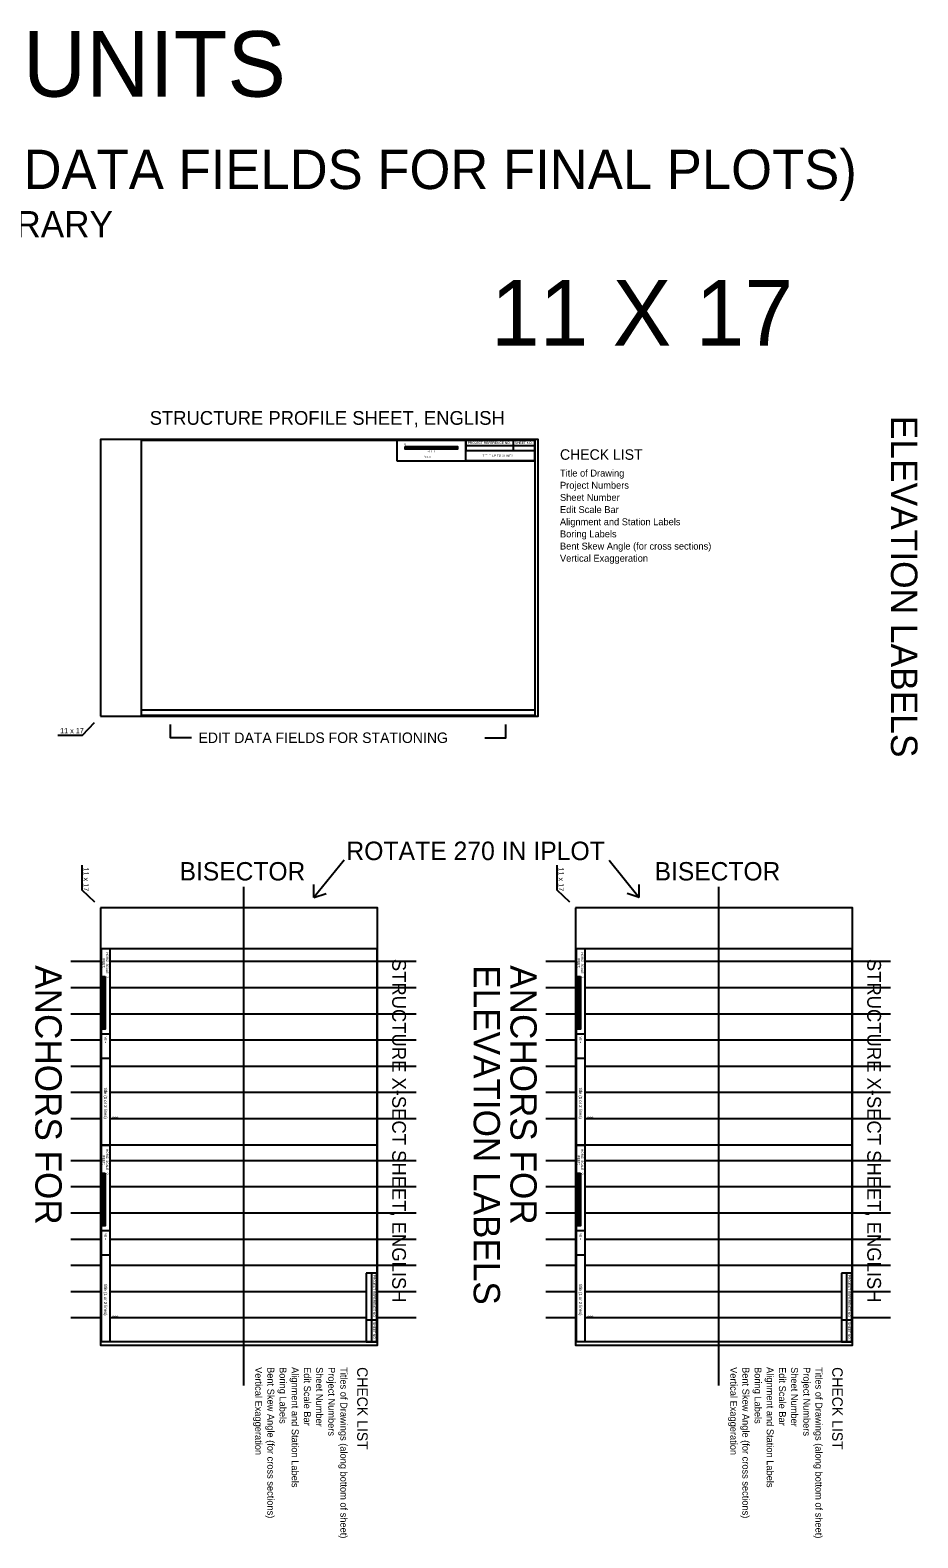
# Model space of a CAD drawing. Extents: x 278618 to 280654, y 171155 to 171855.
# Drawn here: x 279201 to 279539, y 171208 to 171783 of the extents above; entities that cross this region are included whole.
import ezdxf

# ---------------------------------------------------------------- set-up
doc = ezdxf.new("R2010")
doc.units = 0
for name, color, linetype in [('Geotech Sheets and Borders Cell', 7, 'Continuous'), ('Prop Strc Sect_ Grid - minor', 7, 'Continuous'), ('Prop Strc Sect_ Misc - Drafting Aid (dashed line)', 7, 'Continuous'), ('Prop Strc Sect_ Misc - User Comment (Tx - large)', 7, 'Continuous'), ('Prop Strc Sect_ Misc - User Comment (Tx - small)', 7, 'Continuous'), ('Scratch_Level_0', 7, 'Continuous'), ('Scratch_Level_2', 7, 'Continuous'), ('Scratch_Level_4', 7, 'Continuous'), ('Sheet Plot Border Inside CELL', 7, 'Continuous')]:
    doc.layers.add(name, color=color, linetype=linetype)

msp = doc.modelspace()

# ---------------------------------------------------------------- linework, layer by layer
at = {"layer": 'Geotech Sheets and Borders Cell'}
for p, q in [((279366.85, 171624.51), (279393.15, 171624.51)), ((279384.86, 171626.51), (279384.86, 171622.51)), ((279243.15, 171523.66), (279393.15, 171523.66)), ((279231.12, 171399.92), (279227.92, 171399.92)), ((279231.12, 171399.92), (279227.92, 171399.92)), ((279412.21, 171399.92), (279409, 171399.92)), ((279412.21, 171399.92), (279409, 171399.92)), ((279231.12, 171390.69), (279227.92, 171390.69)), ((279412.21, 171390.69), (279409, 171390.69)), ((279332.92, 171357.58), (279227.92, 171357.58)), ((279514, 171357.58), (279409, 171357.58)), ((279231.12, 171324.92), (279227.92, 171324.92)), ((279412.21, 171324.92), (279409, 171324.92)), ((279231.12, 171315.69), (279227.92, 171315.69)), ((279412.21, 171315.69), (279409, 171315.69)), ((279330.92, 171308.88), (279330.92, 171282.58)), ((279512, 171308.88), (279512, 171282.58)), ((279332.92, 171290.87), (279328.92, 171290.87)), ((279514, 171290.87), (279510, 171290.87))]:
    msp.add_line(p, q, dxfattribs=at)
for points in [[(279243.15, 171626.51), (279393.15, 171626.51), (279393.15, 171521.51), (279243.15, 171521.51)], [(279340.56, 171618.61), (279393.15, 171618.61), (279393.15, 171626.51), (279340.56, 171626.51)], [(279343.7, 171624.05), (279363.7, 171624.05), (279363.7, 171623.05), (279343.7, 171623.05)], [(279343.7, 171624.05), (279353.7, 171624.05), (279353.7, 171623.55), (279343.7, 171623.55)], [(279366.85, 171622.51), (279393.15, 171622.51), (279393.15, 171626.51), (279366.85, 171626.51)], [(279366.85, 171626.51), (279393.15, 171626.51), (279393.15, 171618.61), (279366.85, 171618.61)], [(279353.7, 171623.55), (279363.7, 171623.55), (279363.7, 171623.05), (279353.7, 171623.05)], [(279332.92, 171432.58), (279332.92, 171282.58), (279227.92, 171282.58), (279227.92, 171432.58)], [(279231.12, 171432.58), (279231.12, 171357.58), (279227.92, 171357.58), (279227.92, 171432.58)], [(279514, 171432.58), (279514, 171282.58), (279409, 171282.58), (279409, 171432.58)], [(279412.21, 171432.58), (279412.21, 171357.58), (279409, 171357.58), (279409, 171432.58)], [(279229.41, 171421.9), (279229.41, 171401.9), (279228.41, 171401.9), (279228.41, 171421.9)], [(279229.41, 171421.9), (279229.41, 171411.9), (279228.91, 171411.9), (279228.91, 171421.9)], [(279410.5, 171421.9), (279410.5, 171401.9), (279409.5, 171401.9), (279409.5, 171421.9)], [(279410.5, 171421.9), (279410.5, 171411.9), (279410, 171411.9), (279410, 171421.9)], [(279228.91, 171411.9), (279228.91, 171401.9), (279228.41, 171401.9), (279228.41, 171411.9)], [(279410, 171411.9), (279410, 171401.9), (279409.5, 171401.9), (279409.5, 171411.9)], [(279231.12, 171357.58), (279231.12, 171282.58), (279227.92, 171282.58), (279227.92, 171357.58)], [(279412.21, 171357.58), (279412.21, 171282.58), (279409, 171282.58), (279409, 171357.58)], [(279229.41, 171346.9), (279229.41, 171326.9), (279228.41, 171326.9), (279228.41, 171346.9)], [(279229.41, 171346.9), (279229.41, 171336.9), (279228.91, 171336.9), (279228.91, 171346.9)], [(279410.5, 171346.9), (279410.5, 171326.9), (279409.5, 171326.9), (279409.5, 171346.9)], [(279410.5, 171346.9), (279410.5, 171336.9), (279410, 171336.9), (279410, 171346.9)], [(279228.91, 171336.9), (279228.91, 171326.9), (279228.41, 171326.9), (279228.41, 171336.9)], [(279410, 171336.9), (279410, 171326.9), (279409.5, 171326.9), (279409.5, 171336.9)], [(279328.92, 171308.88), (279328.92, 171282.58), (279332.92, 171282.58), (279332.92, 171308.88)], [(279510, 171308.88), (279510, 171282.58), (279514, 171282.58), (279514, 171308.88)]]:
    msp.add_lwpolyline(points, close=True, dxfattribs=at)
at = {"layer": 'Prop Strc Sect_ Grid - minor'}
for p, q in [((279332.92, 171427.66), (279231.12, 171427.66)), ((279514, 171427.66), (279412.21, 171427.66)), ((279332.92, 171417.66), (279231.12, 171417.66)), ((279514, 171417.66), (279412.21, 171417.66)), ((279332.92, 171407.66), (279231.12, 171407.66)), ((279514, 171407.66), (279412.21, 171407.66)), ((279332.92, 171397.66), (279231.12, 171397.66)), ((279514, 171397.66), (279412.21, 171397.66)), ((279332.92, 171387.66), (279231.12, 171387.66)), ((279514, 171387.66), (279412.21, 171387.66)), ((279332.92, 171377.66), (279231.12, 171377.66)), ((279514, 171377.66), (279412.21, 171377.66)), ((279332.92, 171367.66), (279231.12, 171367.66)), ((279514, 171367.66), (279412.21, 171367.66)), ((279332.92, 171351.72), (279231.12, 171351.72)), ((279514, 171351.72), (279412.21, 171351.72)), ((279332.92, 171341.72), (279231.12, 171341.72)), ((279514, 171341.72), (279412.21, 171341.72)), ((279332.92, 171331.72), (279231.12, 171331.72)), ((279514, 171331.72), (279412.21, 171331.72)), ((279332.92, 171321.72), (279231.12, 171321.72)), ((279514, 171321.72), (279412.21, 171321.72)), ((279332.92, 171311.72), (279231.12, 171311.72)), ((279514, 171311.72), (279412.21, 171311.72)), ((279328.92, 171301.72), (279231.12, 171301.72)), ((279510, 171301.72), (279412.21, 171301.72)), ((279328.92, 171291.72), (279231.12, 171291.72)), ((279510, 171291.72), (279412.21, 171291.72))]:
    msp.add_line(p, q, dxfattribs=at)
at = {"layer": 'Prop Strc Sect_ Misc - Drafting Aid (dashed line)'}
for p, q in [((279282.08, 171456.11), (279282.08, 171265.99)), ((279463.17, 171456.11), (279463.17, 171265.99)), ((279227.92, 171427.66), (279216.29, 171427.66)), ((279233.2, 171427.66), (279231.12, 171427.66)), ((279347.88, 171427.66), (279330.96, 171427.66)), ((279409, 171427.66), (279397.38, 171427.66)), ((279414.29, 171427.66), (279412.21, 171427.66)), ((279528.75, 171427.66), (279511.83, 171427.66)), ((279227.92, 171417.66), (279216.29, 171417.66)), ((279233.2, 171417.66), (279231.12, 171417.66)), ((279347.88, 171417.66), (279330.96, 171417.66)), ((279409, 171417.66), (279397.38, 171417.66)), ((279414.29, 171417.66), (279412.21, 171417.66)), ((279528.75, 171417.66), (279511.83, 171417.66)), ((279227.92, 171407.66), (279216.29, 171407.66)), ((279233.2, 171407.66), (279231.12, 171407.66)), ((279347.88, 171407.66), (279330.96, 171407.66)), ((279409, 171407.66), (279397.38, 171407.66)), ((279414.29, 171407.66), (279412.21, 171407.66)), ((279528.75, 171407.66), (279511.83, 171407.66)), ((279227.92, 171397.66), (279216.29, 171397.66)), ((279233.2, 171397.66), (279231.12, 171397.66)), ((279347.88, 171397.66), (279330.96, 171397.66)), ((279409, 171397.66), (279397.38, 171397.66)), ((279414.29, 171397.66), (279412.21, 171397.66)), ((279528.75, 171397.66), (279511.83, 171397.66)), ((279227.92, 171387.66), (279216.29, 171387.66)), ((279233.2, 171387.66), (279231.12, 171387.66)), ((279347.88, 171387.66), (279330.96, 171387.66)), ((279409, 171387.66), (279397.38, 171387.66)), ((279414.29, 171387.66), (279412.21, 171387.66)), ((279528.75, 171387.66), (279511.83, 171387.66)), ((279227.92, 171377.66), (279216.29, 171377.66)), ((279233.2, 171377.66), (279231.12, 171377.66)), ((279347.88, 171377.66), (279330.96, 171377.66)), ((279409, 171377.66), (279397.38, 171377.66)), ((279414.29, 171377.66), (279412.21, 171377.66)), ((279528.75, 171377.66), (279511.83, 171377.66)), ((279227.92, 171367.66), (279216.29, 171367.66)), ((279233.2, 171367.66), (279231.12, 171367.66)), ((279347.88, 171367.66), (279330.96, 171367.66)), ((279409, 171367.66), (279397.38, 171367.66)), ((279414.29, 171367.66), (279412.21, 171367.66)), ((279528.75, 171367.66), (279511.83, 171367.66)), ((279227.92, 171351.72), (279216.29, 171351.72)), ((279233.2, 171351.72), (279231.12, 171351.72)), ((279347.88, 171351.72), (279330.96, 171351.72)), ((279409, 171351.72), (279397.38, 171351.72)), ((279414.29, 171351.72), (279412.21, 171351.72)), ((279528.75, 171351.72), (279511.83, 171351.72)), ((279227.92, 171341.72), (279216.29, 171341.72)), ((279233.2, 171341.72), (279231.12, 171341.72)), ((279347.88, 171341.72), (279330.96, 171341.72)), ((279409, 171341.72), (279397.38, 171341.72)), ((279414.29, 171341.72), (279412.21, 171341.72)), ((279528.75, 171341.72), (279511.83, 171341.72)), ((279227.92, 171331.72), (279216.29, 171331.72)), ((279233.2, 171331.72), (279231.12, 171331.72)), ((279347.88, 171331.72), (279330.96, 171331.72)), ((279409, 171331.72), (279397.38, 171331.72)), ((279414.29, 171331.72), (279412.21, 171331.72)), ((279528.75, 171331.72), (279511.83, 171331.72)), ((279227.92, 171321.72), (279216.29, 171321.72)), ((279233.2, 171321.72), (279231.12, 171321.72)), ((279347.88, 171321.72), (279330.96, 171321.72)), ((279409, 171321.72), (279397.38, 171321.72)), ((279414.29, 171321.72), (279412.21, 171321.72)), ((279528.75, 171321.72), (279511.83, 171321.72)), ((279227.92, 171311.72), (279216.29, 171311.72)), ((279233.2, 171311.72), (279231.12, 171311.72)), ((279347.88, 171311.72), (279330.96, 171311.72)), ((279409, 171311.72), (279397.38, 171311.72)), ((279414.29, 171311.72), (279412.21, 171311.72)), ((279528.75, 171311.72), (279511.83, 171311.72)), ((279227.92, 171301.72), (279216.29, 171301.72)), ((279233.2, 171301.72), (279231.12, 171301.72)), ((279347.88, 171301.72), (279332.92, 171301.72)), ((279409, 171301.72), (279397.38, 171301.72)), ((279414.29, 171301.72), (279412.21, 171301.72)), ((279528.75, 171301.72), (279514, 171301.72)), ((279227.92, 171291.72), (279216.29, 171291.72)), ((279233.2, 171291.72), (279231.12, 171291.72)), ((279347.88, 171291.72), (279332.92, 171291.72)), ((279409, 171291.72), (279397.38, 171291.72)), ((279414.29, 171291.72), (279412.21, 171291.72)), ((279528.75, 171291.72), (279514, 171291.72))]:
    msp.add_line(p, q, dxfattribs=at)
at = {"layer": 'Prop Strc Sect_ Misc - User Comment (Tx - small)'}
for p, q in [((279320.49, 171466.35), (279308.95, 171452.11)), ((279421.43, 171466.35), (279432.97, 171452.11)), ((279308.95, 171452.11), (279308.95, 171457)), ((279308.95, 171452.11), (279313.61, 171453.59)), ((279432.97, 171452.11), (279428.31, 171453.59)), ((279432.97, 171452.11), (279432.97, 171457))]:
    msp.add_line(p, q, dxfattribs=at)
at = {"layer": 'Scratch_Level_0'}
for p, q in [((279394.4, 171626.79), (279394.4, 171626.79)), ((279227.63, 171521.23), (279227.63, 171521.23)), ((279227.63, 171448.1), (279227.63, 171448.1)), ((279408.72, 171448.1), (279408.72, 171448.1)), ((279333.2, 171281.33), (279333.2, 171281.33)), ((279514.29, 171281.33), (279514.29, 171281.33))]:
    msp.add_line(p, q, dxfattribs=at)
for points in [[(279211.37, 171514.04), (279220.75, 171514.04), (279225.34, 171518.83)], [(279220.44, 171464.37), (279220.44, 171454.98), (279225.24, 171450.39)], [(279401.53, 171464.37), (279401.53, 171454.98), (279406.33, 171450.39)]]:
    msp.add_lwpolyline(points, dxfattribs=at)
at = {"layer": 'Scratch_Level_4'}
for points in [[(279262.24, 171513.02), (279254.21, 171513.02), (279254.21, 171518.1)], [(279374.06, 171513.02), (279382.08, 171513.02), (279382.08, 171518.1)]]:
    msp.add_lwpolyline(points, dxfattribs=at)
at = {"layer": 'Sheet Plot Border Inside CELL'}
for points in [[(279227.63, 171521.23), (279394.4, 171521.23), (279394.4, 171626.79), (279227.63, 171626.79)], [(279227.63, 171448.1), (279227.63, 171281.33), (279333.2, 171281.33), (279333.2, 171448.1)], [(279408.72, 171448.1), (279408.72, 171281.33), (279514.29, 171281.33), (279514.29, 171448.1)]]:
    msp.add_lwpolyline(points, close=True, dxfattribs=at)

# ---------------------------------------------------------------- texts
at = {"layer": 'Geotech Sheets and Borders Cell'}
for s, height, p in [('0', 0.84, (279343.46, 171624.52)), ('PROJECT REFERENCE NO.', 0.9, (279367.56, 171625.06)), ('SHEET NO.', 0.9, (279385.58, 171625.06)), ('VE =  ', 0.84, (279351, 171619.82)), ('FEET', 0.84, (279352.15, 171621.83)), ('###', 1.008, (279232.03, 171367.66)), ('###', 1.008, (279413.11, 171367.66)), ('###', 1.008, (279232.03, 171291.72)), ('###', 1.008, (279413.11, 171291.72))]:
    msp.add_text(s, height=height, dxfattribs=at).set_placement(p)
for s, height, rotation, p in [('TITLE UP TO 3 LINES', 0.84, 360, (279373.28, 171620.16)), ('(FEET)', 0.84, 270, (279228.46, 171428.93)), ('HORIZ. SCALE', 0.84, 270, (279229.7, 171431.14)), ('(FEET)', 0.84, 270, (279409.54, 171428.93)), ('HORIZ. SCALE', 0.84, 270, (279410.79, 171431.14)), ('0', 0.84, 270, (279229.89, 171422.14)), ('0', 0.84, 270, (279410.97, 171422.14)), ('VE =  ', 0.84, 270, (279229.08, 171399.07)), ('VE =  ', 0.84, 270, (279410.16, 171399.07)), ('title (1 or 2 lines) ', 1.1681, 270, (279228.91, 171379.6)), ('title (1 or 2 lines) ', 1.1681, 270, (279410, 171379.6)), ('(FEET)', 0.84, 270, (279228.46, 171353.93)), ('HORIZ. SCALE', 0.84, 270, (279229.7, 171356.14)), ('(FEET)', 0.84, 270, (279409.54, 171353.93)), ('HORIZ. SCALE', 0.84, 270, (279410.79, 171356.14)), ('0', 0.84, 270, (279229.89, 171347.14)), ('0', 0.84, 270, (279410.97, 171347.14)), ('VE =  ', 0.84, 270, (279229.08, 171324.07)), ('VE =  ', 0.84, 270, (279410.16, 171324.07)), ('PROJECT REFERENCE NO.', 0.9, 270, (279331.47, 171308.17)), ('PROJECT REFERENCE NO.', 0.9, 270, (279512.55, 171308.17)), ('title (1 or 2 lines) ', 1.1681, 270, (279228.91, 171304.6)), ('title (1 or 2 lines) ', 1.1681, 270, (279410, 171304.6)), ('SHEET NO.', 0.9, 270, (279331.47, 171290.16)), ('SHEET NO.', 0.9, 270, (279512.55, 171290.16))]:
    msp.add_text(s, height=height, rotation=rotation, dxfattribs=at).set_placement(p)
at = {"layer": 'Prop Strc Sect_ Misc - User Comment (Tx - large)'}
for s, height, p in [('ENGLISH UNITS', 25, (279041.91, 171757.51)), ('(TURN OFF DRAFTING AID LEVELS and DATA FIELDS FOR FINAL PLOTS)', 15, (278817.07, 171722.28)), ('11 X 17', 25, (279376.38, 171662.6))]:
    msp.add_text(s, height=height, dxfattribs=at).set_placement(p)
at = {"layer": 'Prop Strc Sect_ Misc - User Comment (Tx - small)'}
for s, height, p in [('ELEMENT LIBRARY', 10, (279108.22, 171703.88)), ('ROTATE 270 IN IPLOT', 7.0538, (279321.29, 171466.35)), ('BISECTOR', 7.009, (279257.74, 171458.59)), ('BISECTOR', 7.009, (279438.83, 171458.59))]:
    msp.add_text(s, height=height, dxfattribs=at).set_placement(p)
for s, height, p in [('ELEVATION LABELS', 10.0769, (279528.93, 171635.81)), ('ANCHORS FOR', 10.0124, (279202.77, 171426.25)), ('ELEVATION LABELS', 10.0124, (279369.84, 171426.25)), ('ANCHORS FOR', 10.0124, (279383.86, 171426.25))]:
    msp.add_text(s, height=height, rotation=270, dxfattribs=at).set_placement(p)
at = {"layer": 'Scratch_Level_0'}
msp.add_text('11 x 17', height=2, dxfattribs=at).set_placement((279212.18, 171514.71))
for p in [(279221.11, 171463.55), (279402.2, 171463.55)]:
    msp.add_text('11 x 17', height=2, rotation=270, dxfattribs=at).set_placement(p)
at = {"layer": 'Scratch_Level_2'}
msp.add_text('STRUCTURE PROFILE SHEET, ENGLISH', height=5.25, dxfattribs=at).set_placement((279246.34, 171632.37))
for p in [(279338.78, 171428.69), (279519.87, 171428.69)]:
    msp.add_text('STRUCTURE X-SECT SHEET, ENGLISH', height=5.25, rotation=270, dxfattribs=at).set_placement(p)
at = {"layer": 'Scratch_Level_4'}
for s, height, p in [('CHECK LIST', 4, (279402.74, 171619.03)), ('Title of Drawing', 2.64, (279402.74, 171612.63)), ('Project Numbers', 2.64, (279402.74, 171607.99)), ('Sheet Number', 2.64, (279402.74, 171603.35)), ('Edit Scale Bar', 2.64, (279402.74, 171598.71)), ('Alignment and Station Labels', 2.64, (279402.74, 171594.07)), ('Boring Labels', 2.64, (279402.74, 171589.43)), ('Bent Skew Angle (for cross sections)', 2.64, (279402.74, 171584.79)), ('Vertical Exaggeration', 2.64, (279402.74, 171580.15)), ('EDIT DATA FIELDS FOR STATIONING', 4, (279264.92, 171511.02))]:
    msp.add_text(s, height=height, dxfattribs=at).set_placement(p)
for s, height, p in [('Vertical Exaggeration', 2.64, (279286.55, 171272.99)), ('Bent Skew Angle (for cross sections)', 2.64, (279291.19, 171272.99)), ('Boring Labels', 2.64, (279295.83, 171272.99)), ('Alignment and Station Labels', 2.64, (279300.47, 171272.99)), ('Edit Scale Bar', 2.64, (279305.11, 171272.99)), ('Sheet Number', 2.64, (279309.75, 171272.99)), ('Project Numbers', 2.64, (279314.39, 171272.99)), ('Titles of Drawings (along bottom of sheet)', 2.64, (279319.03, 171272.99)), ('CHECK LIST', 4, (279325.43, 171272.99)), ('Vertical Exaggeration', 2.64, (279467.64, 171272.99)), ('Bent Skew Angle (for cross sections)', 2.64, (279472.28, 171272.99)), ('Boring Labels', 2.64, (279476.92, 171272.99)), ('Alignment and Station Labels', 2.64, (279481.56, 171272.99)), ('Edit Scale Bar', 2.64, (279486.2, 171272.99)), ('Sheet Number', 2.64, (279490.84, 171272.99)), ('Project Numbers', 2.64, (279495.48, 171272.99)), ('Titles of Drawings (along bottom of sheet)', 2.64, (279500.12, 171272.99)), ('CHECK LIST', 4, (279506.52, 171272.99))]:
    msp.add_text(s, height=height, rotation=270, dxfattribs=at).set_placement(p)

doc.saveas('drawing.dxf')
